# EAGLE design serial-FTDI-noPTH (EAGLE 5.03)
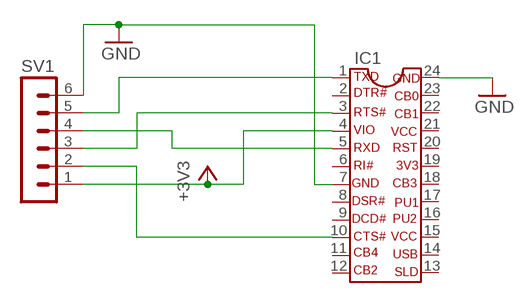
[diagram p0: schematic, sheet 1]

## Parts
IC1  EE2PARTS_UM232R-6  [EE2PARTS_DIL24-6]
SV1  MA06-1  [MA06-1]

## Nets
+3V3: IC1.4 SV1.1
GND: IC1.7 IC1.24 SV1.6
N$1: IC1.10 SV1.2
N$2: IC1.3 SV1.3
N$3: IC1.5 SV1.4
N$4: IC1.1 SV1.5
Unconnected: IC1.2 IC1.6 IC1.8 IC1.9 IC1.11 IC1.12 IC1.13 IC1.14 IC1.15 IC1.16 IC1.17 IC1.18 IC1.19 IC1.20 IC1.21 IC1.22 IC1.23

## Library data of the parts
IC1 = zcontr-noPTH_lib:EE2PARTS_UM232R: USB to Serial Module Provides easy USB interface to serial (UART) with power supply
SV1 = con-lstb:MA06-1: PIN HEADER

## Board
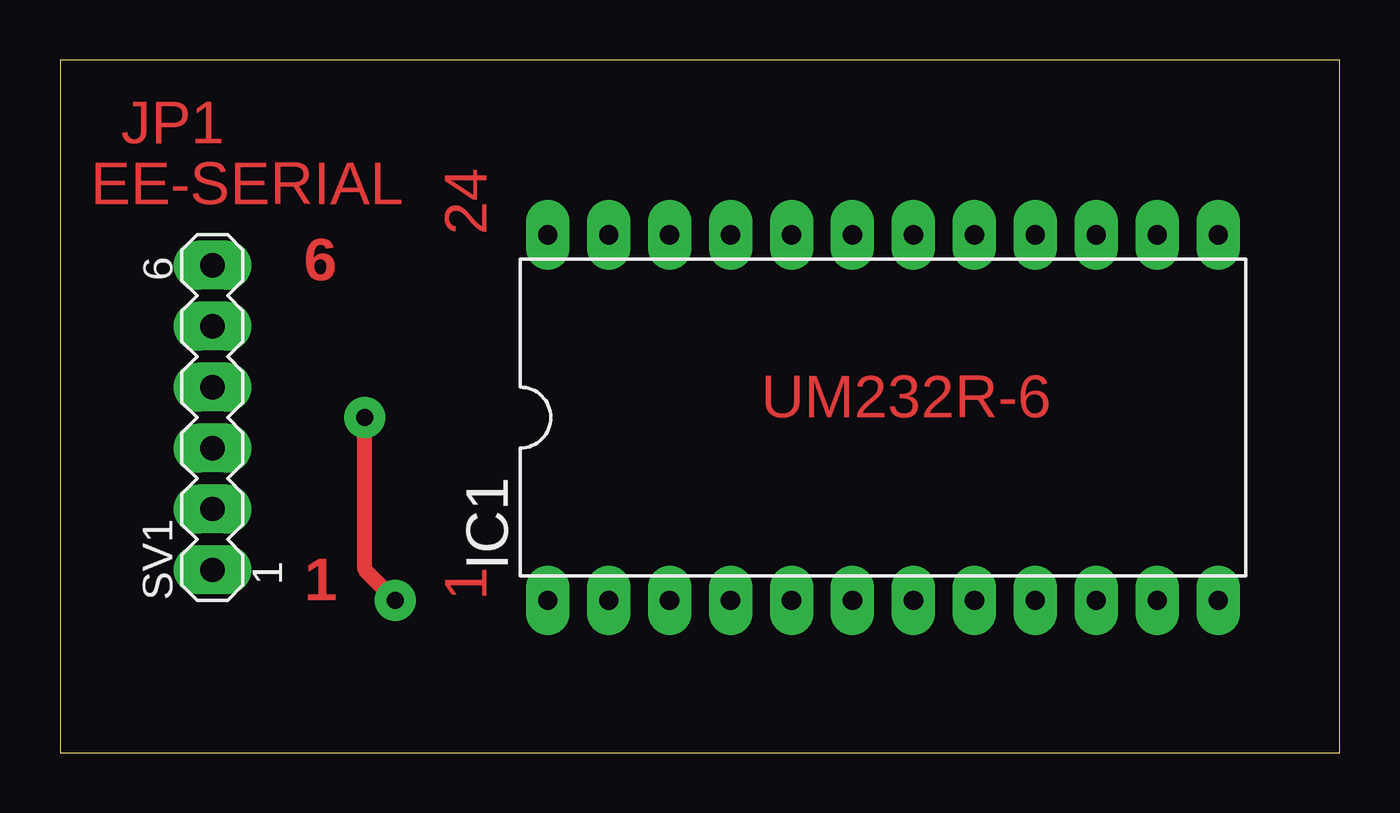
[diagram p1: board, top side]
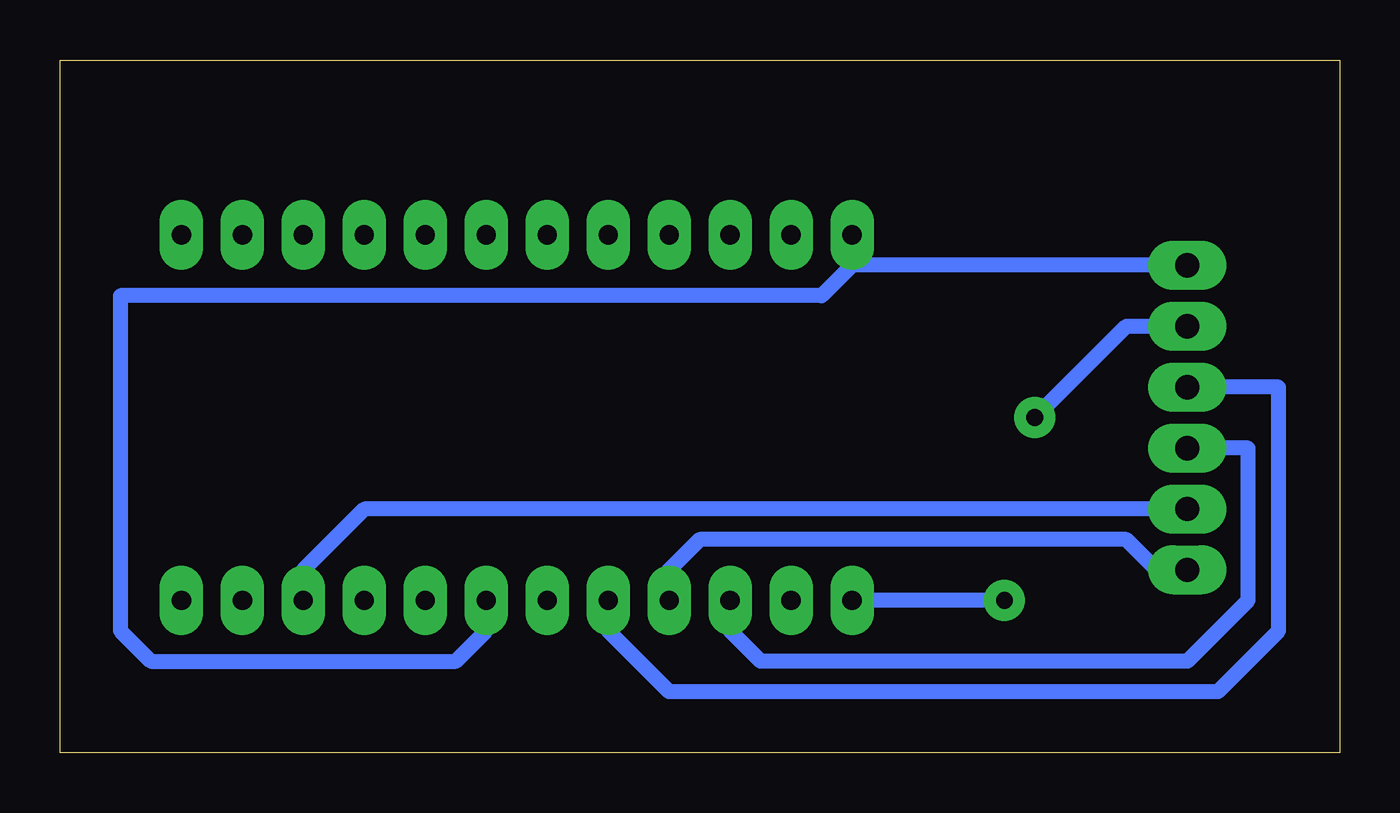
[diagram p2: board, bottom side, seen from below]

Size 53.32 x 28.88 mm. Coordinates in mm from the lower left corner, seen from the top.
Outline: 0,0 53.32,0 53.32,28.88 0,28.88 0,0
Copper layers (1*16): Top 0.035mm / dielectric 1.5mm / Bottom 0.035mm
Design rules "zigbit_rules *": minimum track width 25mil, minimum drill 0.7mm, track to track 13mil, track to pad 13mil, pad to pad 13mil, via to via 13mil, smd to smd 0mil, copper to edge 10mil, drill to drill 10mil, minimum pad ring 20mil, minimum via ring 20mil, stop-mask expansion 0mil, vias tented up to drill 0mil, thermal gap 15mil
tRestrict: area 19,20.3 to 49.5,22.9; area 19,5.1 to 49.5,7.6; area 3.8,6.3 to 8.9,21.6

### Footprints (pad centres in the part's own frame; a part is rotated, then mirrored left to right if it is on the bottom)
EE2PARTS_DIL24-6 = drill 0.8 long: 1 -13.97,-7.62; 2 -11.43,-7.62; 3 -8.89,-7.62; 4 -6.35,-7.62; 5 -3.81,-7.62; 6 -1.27,-7.62; 7 1.27,-7.62; 8 3.81,-7.62; 9 6.35,-7.62; 10 8.89,-7.62; 11 11.43,-7.62; 12 13.97,-7.62; 13 13.97,7.62; 14 11.43,7.62; 15 8.89,7.62; 16 6.35,7.62; 17 3.81,7.62; 18 1.27,7.62; 19 -1.27,7.62; 20 -3.81,7.62; 21 -6.35,7.62; 22 -8.89,7.62; 23 -11.43,7.62; 24 -13.97,7.62
MA06-1 = drill 1.016 long: 1 -6.35,0; 2 -3.81,0; 3 -1.27,0; 4 1.27,0; 5 3.81,0; 6 6.35,0

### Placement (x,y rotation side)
IC1  34.29,13.97 0 top
SV1  6.35,13.97 90 top

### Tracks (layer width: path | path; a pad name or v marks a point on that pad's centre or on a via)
+3V3
  Bottom 0.635: IC1.4 27.94,7.62 26.67,8.89 8.89,8.89 7.62,7.62 SV1.1
GND
  Bottom 0.635: 20.32,20.32 21.59,19.05 50.8,19.05 50.8,5.08 49.53,3.81 36.83,3.81 35.56,5.08 IC1.7 | SV1.6 20.32,20.32 | 20.32,20.32 IC1.24
N$1
  Bottom 0.635: IC1.10 43.18,7.62 40.64,10.16 SV1.2
N$2
  Bottom 0.635: IC1.3 25.4,5.08 24.13,3.81 6.35,3.81 3.81,6.35 3.81,12.7 SV1.3
N$3
  Bottom 0.635: IC1.5 30.48,5.08 27.94,2.54 5.08,2.54 2.54,5.08 2.54,15.24 SV1.4
N$4  (via drill 0.7)
  Top 0.635: v13.97,6.35 12.7,7.62 v12.7,13.97
  Bottom 0.635: v13.97,6.35 IC1.1 | v12.7,13.97 8.89,17.78 SV1.5

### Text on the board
Top: JP1 | EE-SERIAL | 24 | 6 | UM232R-6 | 1 | 1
